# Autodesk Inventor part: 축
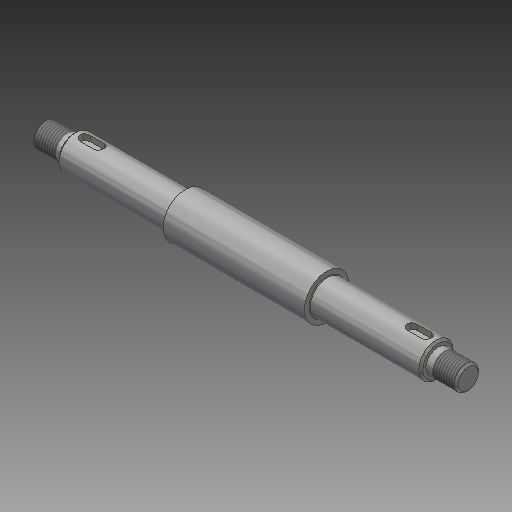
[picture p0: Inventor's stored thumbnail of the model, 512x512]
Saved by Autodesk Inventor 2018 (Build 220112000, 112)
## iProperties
Created: 2018-11
Part Number: 축
Material: 강철, 연강
Document SubType Name: Modeling
Designer: mduedu
Density: 1 g/cm^3
Appearance: 강철
Author: mduedu
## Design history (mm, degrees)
sketch "스케치1"
  geometry: L1 (-35, 0)-(35, 0); L2 (35, 0)-(35, 11); L3 (35, 11)-(-35, 11); L4 (-35, 11)-(-35, 0); L5 (-35, 0)-(-90, 0); L6 (-90, 0)-(-90, 8.5); L7 (-90, 8.5)-(-35, 8.5); L8 (-35, 8.5)-(-35, 0); L9 (-90, 0)-(-105, 0); L10 (-105, 0)-(-105, 6); L11 (-105, 6)-(-90, 6); L12 (-90, 6)-(-90, 0); L13 (0, 0)-(0, 11); L14 (35, 0)-(90, 0); L15 (90, 0)-(90, 8.5); L16 (90, 8.5)-(35, 8.5); L17 (35, 8.5)-(35, 0); L18 (90, 0)-(105, 0); L19 (105, 0)-(105, 6); L20 (105, 6)-(90, 6); L21 (90, 6)-(90, 0); 1 further point
  constraints: 42 end point, 6 parallel, 6 symmetric about line, 3 horizontal, 3 perpendicular, 2 midpoint, 1 coincident
  dimensions: "d0" = 22 diameter of L3 L1; "d2" = 17 diameter of L7 L5; "d3" = 12 diameter of L11 L9; "d4" = 70 distance of L2.end L3.end; "d5" = 55 distance of L6.end L7.end; "d6" = 210 distance between parallel lines of L19 L10
revolve "회전1" sketch "스케치1" stored, may be unused: angle "d7" = 90 deg
fillet "모깎기1" dims "d8" = 0.3
node "작업 평면1"
sketch "스케치2" dims "d11" = 12
  geometry: L1 (15, 2.5)-(22, 2.5); L2 (22, 2.5)-(22, -2.5); L3 (22, -2.5)-(15, -2.5); L4 (15, -2.5)-(15, 2.5); L5 (27.5, 8.5)-(27.5, -8.5) reference; 3 further points
  constraints: 8 end point, 2 midpoint, 2 parallel, 2 vertical alignment, 1 horizontal, 1 horizontal alignment, 1 perpendicular, 4 other
  dimensions: "d9" = 3 dimension on L5; "d10" = 5 distance between parallel lines of L3 L1
extrude "돌출1" cut sketch "스케치2" distance "d12" = 3; taper "d13" = 0 deg
chamfer "모따기1" distance "d14" = 1; stored, may be unused: second distance "d15" = 2, angle "d16" = 45 deg
feature "스레드1" dims "d17" = 12, "d18" = 0
feature "스레드2" dims "d19" = 12, "d20" = 0
chamfer "모따기2" distance "d21" = 1; stored, may be unused: second distance "d22" = 2, angle "d23" = 45 deg
node "솔리드1"
mirror "대칭1"
